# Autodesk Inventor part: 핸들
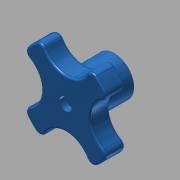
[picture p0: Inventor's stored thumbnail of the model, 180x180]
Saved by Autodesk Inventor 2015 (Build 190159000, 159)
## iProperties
Created: 2018-01
Part Number: 핸들
Material: ABS 플라스틱
Document SubType Name: Modeling
Designer: mduedu
Density: 1 g/cm^3
Appearance: 청록색
Author: mduedu
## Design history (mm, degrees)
sketch "스케치1"
  geometry: C1 r 10 at (0, 0); C2 r 25 at (0, 0); 1 further point
  constraints: 2 centre point, 2 coincident
  dimensions: "d0" = 20 diameter of C1; "d1" = 50 diameter of C2
extrude "돌출1" new body sketch "스케치1" distance "d2" = 15; taper "d3" = 0 deg
extrude "돌출2" join sketch "스케치1" distance "d4" = 10; taper "d5" = 0 deg
sketch "스케치2" dims "d8" = 15
  geometry: L1 (-6, -6)-(-4.5, -6); L2 (6, -6)-(6, -4.5); L3 (6, 6)-(4.5, 6); L4 (-6, 6)-(-6, 4.5); L5 (-6, -6)-(6, 6); L6 (6, -6)-(-6, 6); L7 (-4.5, 6)-(-6, 6); L8 (4.5, 6)-(-4.5, 6); L9 (6, 4.5)-(6, 6); L10 (6, -4.5)-(6, 4.5); L11 (4.5, -6)-(6, -6); L12 (-4.5, -6)-(4.5, -6); L13 (-6, -4.5)-(-6, -6); L14 (-6, 4.5)-(-6, -4.5); 2 further points
  constraints: 28 end point, 18 parallel, 9 perpendicular, 3 horizontal, 2 midpoint, 1 coincident, 10 other
  dimensions: "d6" = 12 distance of L4.start L3.start; "d7" = 12 distance of L3.start L2.start
extrude "돌출3" cut sketch "스케치2" distance "d9" = 15; taper "d10" = 0 deg
sketch "스케치3"
  geometry: C1 r 12.5 at (25, 0); 2 further points
  constraints: 2 horizontal alignment, 1 centre point, 1 other
  dimensions: "d14" = 25 diameter of C1
extrude "돌출4" cut sketch "스케치3" stored distance "d15" = 15; taper "d16" = 0 deg
fillet "모깎기1" dims "d20" = 3
fillet "모깎기2" dims "d24" = 1
sketch "스케치4"
  geometry: 2 further points
  constraints: 1 coincident
sketch "스케치5"
  geometry: 2 further points
  constraints: 1 coincident
hole "구멍1" sketch "스케치5" at (0, 0) diameter "d25" = 3.4; stored, may be unused: countersink angle "d29" = 90 deg, drill point angle "d31" = 0 deg; dims "d26" = 6, "d27" = 6.5, "d28" = 3.4, "d30" = 8
node "솔리드1"
pattern_circular "원형 패턴1" dims angle "d18" = 360 deg
pattern_circular "원형 패턴2" dims angle "d22" = 360 deg
node "투영된 루프1"
